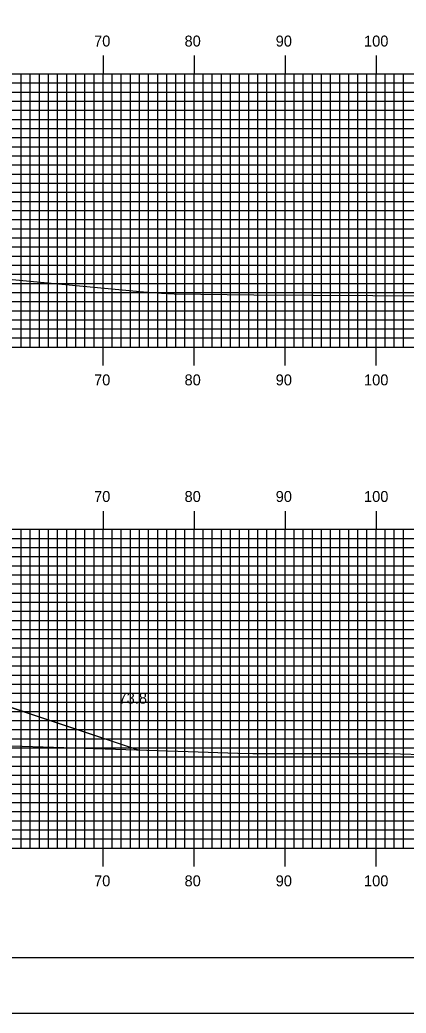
# Model space of a CAD drawing. Extents: x 1813735 to 1814078, y 442591 to 442811.
# Drawn here: x 1813961.3 to 1814003.8, y 442590.5 to 442699.6 of the extents above; entities that cross this region are included whole.
import ezdxf

# ---------------------------------------------------------------- set-up
doc = ezdxf.new("R2010")
doc.units = 0
for name, color, linetype in [('BORDER', 7, 'Continuous'), ('D_Roadway_Centerline', 7, 'Continuous'), ('D_Roadway_SlopeLines', 7, 'Continuous'), ('D_Text_Standard', 7, 'Continuous'), ('H_V ANNOTATION', 7, 'Continuous'), ('MAJOR', 7, 'Continuous'), ('MINOR', 7, 'Continuous'), ('PLOT BOUNDARY', 7, 'Continuous'), ('S_Roadway_Centerline', 7, 'Continuous')]:
    doc.layers.add(name, color=color, linetype=linetype)

msp = doc.modelspace()

# ---------------------------------------------------------------- linework, layer by layer
at = {"layer": 'BORDER'}
msp.add_lwpolyline([(1813750.88, 442596.67), (1814070.88, 442596.67), (1814070.88, 442806.67), (1813750.88, 442806.67)], close=True, dxfattribs=at)
at = {"layer": 'D_Roadway_Centerline'}
msp.add_lwpolyline([(1813843.09, 442623.4), (1813869.5, 442632.2), (1813877.48, 442634.86), (1813880.48, 442634.92), (1813888.48, 442635.08), (1813900.48, 442634.51), (1813912.48, 442633.93), (1813930.42, 442633.07), (1813942.42, 442630.07), (1813942.8, 442629.98), (1813974.32, 442619.44)], dxfattribs=at)
at = {"layer": 'D_Roadway_SlopeLines'}
msp.add_lwpolyline([(1813930.42, 442633.07), (1813942.42, 442630.07), (1813974.32, 442619.44)], dxfattribs=at)
at = {"layer": 'MAJOR'}
for p, q in [((1813970.48, 442695.67), (1813970.48, 442693.67)), ((1813980.48, 442695.67), (1813980.48, 442693.67)), ((1813990.48, 442695.67), (1813990.48, 442693.67)), ((1814000.48, 442695.67), (1814000.48, 442693.67)), ((1813760.48, 442693.67), (1814040.48, 442693.67)), ((1813760.48, 442693.67), (1814040.48, 442693.67)), ((1813970.48, 442663.67), (1813970.48, 442693.67)), ((1813980.48, 442663.67), (1813980.48, 442693.67)), ((1813990.48, 442663.67), (1813990.48, 442693.67)), ((1814000.48, 442663.67), (1814000.48, 442693.67)), ((1813760.48, 442688.67), (1814040.48, 442688.67)), ((1813760.48, 442683.67), (1814040.48, 442683.67)), ((1813760.48, 442678.67), (1814040.48, 442678.67)), ((1813760.48, 442673.67), (1814040.48, 442673.67)), ((1813760.48, 442668.67), (1814040.48, 442668.67)), ((1813760.48, 442663.67), (1814040.48, 442663.67)), ((1813760.48, 442663.67), (1814040.48, 442663.67)), ((1813970.48, 442661.66), (1813970.48, 442663.67)), ((1813980.48, 442661.66), (1813980.48, 442663.67)), ((1813990.48, 442661.66), (1813990.48, 442663.67)), ((1814000.48, 442661.66), (1814000.48, 442663.67)), ((1813970.48, 442645.67), (1813970.48, 442643.67)), ((1813980.48, 442645.67), (1813980.48, 442643.67)), ((1813990.48, 442645.67), (1813990.48, 442643.67)), ((1814000.48, 442645.67), (1814000.48, 442643.67)), ((1813760.48, 442643.67), (1814040.48, 442643.67)), ((1813760.48, 442643.67), (1814040.48, 442643.67)), ((1813970.48, 442608.67), (1813970.48, 442643.67)), ((1813980.48, 442608.67), (1813980.48, 442643.67)), ((1813990.48, 442608.67), (1813990.48, 442643.67)), ((1814000.48, 442608.67), (1814000.48, 442643.67)), ((1813760.48, 442638.67), (1814040.48, 442638.67)), ((1813760.48, 442633.67), (1814040.48, 442633.67)), ((1813760.48, 442628.67), (1814040.48, 442628.67)), ((1813760.48, 442623.67), (1814040.48, 442623.67)), ((1813760.48, 442618.67), (1814040.48, 442618.67)), ((1813760.48, 442613.67), (1814040.48, 442613.67)), ((1813760.48, 442608.67), (1814040.48, 442608.67)), ((1813760.48, 442608.67), (1814040.48, 442608.67)), ((1813970.48, 442606.66), (1813970.48, 442608.67)), ((1813980.48, 442606.66), (1813980.48, 442608.67)), ((1813990.48, 442606.66), (1813990.48, 442608.67)), ((1814000.48, 442606.66), (1814000.48, 442608.67))]:
    msp.add_line(p, q, dxfattribs=at)
at = {"layer": 'MINOR'}
for p, q in [((1813961.48, 442663.67), (1813961.48, 442693.67)), ((1813962.48, 442663.67), (1813962.48, 442693.67)), ((1813963.48, 442663.67), (1813963.48, 442693.67)), ((1813964.48, 442663.67), (1813964.48, 442693.67)), ((1813965.48, 442663.67), (1813965.48, 442693.67)), ((1813966.48, 442663.67), (1813966.48, 442693.67)), ((1813967.48, 442663.67), (1813967.48, 442693.67)), ((1813968.48, 442663.67), (1813968.48, 442693.67)), ((1813969.48, 442663.67), (1813969.48, 442693.67)), ((1813971.48, 442663.67), (1813971.48, 442693.67)), ((1813972.48, 442663.67), (1813972.48, 442693.67)), ((1813973.48, 442663.67), (1813973.48, 442693.67)), ((1813974.48, 442663.67), (1813974.48, 442693.67)), ((1813975.48, 442663.67), (1813975.48, 442693.67)), ((1813976.48, 442663.67), (1813976.48, 442693.67)), ((1813977.48, 442663.67), (1813977.48, 442693.67)), ((1813978.48, 442663.67), (1813978.48, 442693.67)), ((1813979.48, 442663.67), (1813979.48, 442693.67)), ((1813981.48, 442663.67), (1813981.48, 442693.67)), ((1813982.48, 442663.67), (1813982.48, 442693.67)), ((1813983.48, 442663.67), (1813983.48, 442693.67)), ((1813984.48, 442663.67), (1813984.48, 442693.67)), ((1813985.48, 442663.67), (1813985.48, 442693.67)), ((1813986.48, 442663.67), (1813986.48, 442693.67)), ((1813987.48, 442663.67), (1813987.48, 442693.67)), ((1813988.48, 442663.67), (1813988.48, 442693.67)), ((1813989.48, 442663.67), (1813989.48, 442693.67)), ((1813991.48, 442663.67), (1813991.48, 442693.67)), ((1813992.48, 442663.67), (1813992.48, 442693.67)), ((1813993.48, 442663.67), (1813993.48, 442693.67)), ((1813994.48, 442663.67), (1813994.48, 442693.67)), ((1813995.48, 442663.67), (1813995.48, 442693.67)), ((1813996.48, 442663.67), (1813996.48, 442693.67)), ((1813997.48, 442663.67), (1813997.48, 442693.67)), ((1813998.48, 442663.67), (1813998.48, 442693.67)), ((1813999.48, 442663.67), (1813999.48, 442693.67)), ((1814001.48, 442663.67), (1814001.48, 442693.67)), ((1814002.48, 442663.67), (1814002.48, 442693.67)), ((1814003.48, 442663.67), (1814003.48, 442693.67)), ((1813760.48, 442692.67), (1814040.48, 442692.67)), ((1813760.48, 442691.67), (1814040.48, 442691.67)), ((1813760.48, 442690.67), (1814040.48, 442690.67)), ((1813760.48, 442689.67), (1814040.48, 442689.67)), ((1813760.48, 442687.67), (1814040.48, 442687.67)), ((1813760.48, 442686.67), (1814040.48, 442686.67)), ((1813760.48, 442685.67), (1814040.48, 442685.67)), ((1813760.48, 442684.67), (1814040.48, 442684.67)), ((1813760.48, 442682.67), (1814040.48, 442682.67)), ((1813760.48, 442681.67), (1814040.48, 442681.67)), ((1813760.48, 442680.67), (1814040.48, 442680.67)), ((1813760.48, 442679.67), (1814040.48, 442679.67)), ((1813760.48, 442677.67), (1814040.48, 442677.67)), ((1813760.48, 442676.67), (1814040.48, 442676.67)), ((1813760.48, 442675.67), (1814040.48, 442675.67)), ((1813760.48, 442674.67), (1814040.48, 442674.67)), ((1813760.48, 442672.67), (1814040.48, 442672.67)), ((1813760.48, 442671.67), (1814040.48, 442671.67)), ((1813760.48, 442670.67), (1814040.48, 442670.67)), ((1813760.48, 442669.67), (1814040.48, 442669.67)), ((1813760.48, 442667.67), (1814040.48, 442667.67)), ((1813760.48, 442666.67), (1814040.48, 442666.67)), ((1813760.48, 442665.67), (1814040.48, 442665.67)), ((1813760.48, 442664.67), (1814040.48, 442664.67)), ((1813961.48, 442608.67), (1813961.48, 442643.67)), ((1813962.48, 442608.67), (1813962.48, 442643.67)), ((1813963.48, 442608.67), (1813963.48, 442643.67)), ((1813964.48, 442608.67), (1813964.48, 442643.67)), ((1813965.48, 442608.67), (1813965.48, 442643.67)), ((1813966.48, 442608.67), (1813966.48, 442643.67)), ((1813967.48, 442608.67), (1813967.48, 442643.67)), ((1813968.48, 442608.67), (1813968.48, 442643.67)), ((1813969.48, 442608.67), (1813969.48, 442643.67)), ((1813971.48, 442608.67), (1813971.48, 442643.67)), ((1813972.48, 442608.67), (1813972.48, 442643.67)), ((1813973.48, 442608.67), (1813973.48, 442643.67)), ((1813974.48, 442608.67), (1813974.48, 442643.67)), ((1813975.48, 442608.67), (1813975.48, 442643.67)), ((1813976.48, 442608.67), (1813976.48, 442643.67)), ((1813977.48, 442608.67), (1813977.48, 442643.67)), ((1813978.48, 442608.67), (1813978.48, 442643.67)), ((1813979.48, 442608.67), (1813979.48, 442643.67)), ((1813981.48, 442608.67), (1813981.48, 442643.67)), ((1813982.48, 442608.67), (1813982.48, 442643.67)), ((1813983.48, 442608.67), (1813983.48, 442643.67)), ((1813984.48, 442608.67), (1813984.48, 442643.67)), ((1813985.48, 442608.67), (1813985.48, 442643.67)), ((1813986.48, 442608.67), (1813986.48, 442643.67)), ((1813987.48, 442608.67), (1813987.48, 442643.67)), ((1813988.48, 442608.67), (1813988.48, 442643.67)), ((1813989.48, 442608.67), (1813989.48, 442643.67)), ((1813991.48, 442608.67), (1813991.48, 442643.67)), ((1813992.48, 442608.67), (1813992.48, 442643.67)), ((1813993.48, 442608.67), (1813993.48, 442643.67)), ((1813994.48, 442608.67), (1813994.48, 442643.67)), ((1813995.48, 442608.67), (1813995.48, 442643.67)), ((1813996.48, 442608.67), (1813996.48, 442643.67)), ((1813997.48, 442608.67), (1813997.48, 442643.67)), ((1813998.48, 442608.67), (1813998.48, 442643.67)), ((1813999.48, 442608.67), (1813999.48, 442643.67)), ((1814001.48, 442608.67), (1814001.48, 442643.67)), ((1814002.48, 442608.67), (1814002.48, 442643.67)), ((1814003.48, 442608.67), (1814003.48, 442643.67)), ((1813760.48, 442642.67), (1814040.48, 442642.67)), ((1813760.48, 442641.67), (1814040.48, 442641.67)), ((1813760.48, 442640.67), (1814040.48, 442640.67)), ((1813760.48, 442639.67), (1814040.48, 442639.67)), ((1813760.48, 442637.67), (1814040.48, 442637.67)), ((1813760.48, 442636.67), (1814040.48, 442636.67)), ((1813760.48, 442635.67), (1814040.48, 442635.67)), ((1813760.48, 442634.67), (1814040.48, 442634.67)), ((1813760.48, 442632.67), (1814040.48, 442632.67)), ((1813760.48, 442631.67), (1814040.48, 442631.67)), ((1813760.48, 442630.67), (1814040.48, 442630.67)), ((1813760.48, 442629.67), (1814040.48, 442629.67)), ((1813760.48, 442627.67), (1814040.48, 442627.67)), ((1813760.48, 442626.67), (1814040.48, 442626.67)), ((1813760.48, 442625.67), (1814040.48, 442625.67)), ((1813760.48, 442624.67), (1814040.48, 442624.67)), ((1813760.48, 442622.67), (1814040.48, 442622.67)), ((1813760.48, 442621.67), (1814040.48, 442621.67)), ((1813760.48, 442620.67), (1814040.48, 442620.67)), ((1813760.48, 442619.67), (1814040.48, 442619.67)), ((1813760.48, 442617.67), (1814040.48, 442617.67)), ((1813760.48, 442616.67), (1814040.48, 442616.67)), ((1813760.48, 442615.67), (1814040.48, 442615.67)), ((1813760.48, 442614.67), (1814040.48, 442614.67)), ((1813760.48, 442612.67), (1814040.48, 442612.67)), ((1813760.48, 442611.67), (1814040.48, 442611.67)), ((1813760.48, 442610.67), (1814040.48, 442610.67)), ((1813760.48, 442609.67), (1814040.48, 442609.67))]:
    msp.add_line(p, q, dxfattribs=at)
at = {"layer": 'PLOT BOUNDARY'}
msp.add_lwpolyline([(1813734.69, 442590.55), (1814074.69, 442590.55), (1814074.69, 442810.55), (1813734.69, 442810.55)], close=True, dxfattribs=at)
at = {"layer": 'S_Roadway_Centerline'}
for points in [[(1813959.72, 442671.18), (1813974.92, 442669.72), (1813976.9, 442669.58), (1813978.3, 442669.52), (1813987.04, 442669.42), (1814006.66, 442669.31), (1814009.65, 442669.15), (1814022.72, 442668.98), (1814026.17, 442668.98), (1814026.81, 442668.96), (1814028.04, 442669), (1814040.48, 442669.14)], [(1813957, 442620), (1813979.82, 442619.26), (1813985.27, 442619.1), (1813986.92, 442619.05), (1813987.44, 442619.04), (1814001.85, 442619.04), (1814003.18, 442619.02), (1814014.69, 442618.66), (1814017.17, 442618.61), (1814023.13, 442618.56), (1814026.49, 442618.71), (1814037.85, 442618.82), (1814040, 442618.88), (1814040.48, 442618.86)]]:
    msp.add_lwpolyline(points, dxfattribs=at)

# ---------------------------------------------------------------- texts
at = {"layer": 'D_Text_Standard'}
msp.add_text("73.8'", height=1.2, dxfattribs=at).set_placement((1813972.18, 442624.53))
at = {"layer": 'H_V ANNOTATION'}
for s, p in [('70', (1813969.49, 442696.67)), ('80', (1813979.43, 442696.67)), ('90', (1813989.45, 442696.67)), ('100', (1813999.16, 442696.67)), ('70', (1813969.49, 442659.47)), ('80', (1813979.43, 442659.47)), ('90', (1813989.45, 442659.47)), ('100', (1813999.16, 442659.47)), ('70', (1813969.49, 442646.67)), ('80', (1813979.43, 442646.67)), ('90', (1813989.45, 442646.67)), ('100', (1813999.16, 442646.67)), ('70', (1813969.49, 442604.47)), ('80', (1813979.43, 442604.47)), ('90', (1813989.45, 442604.47)), ('100', (1813999.16, 442604.47))]:
    msp.add_text(s, height=1.2, dxfattribs=at).set_placement(p)

doc.saveas('drawing.dxf')
